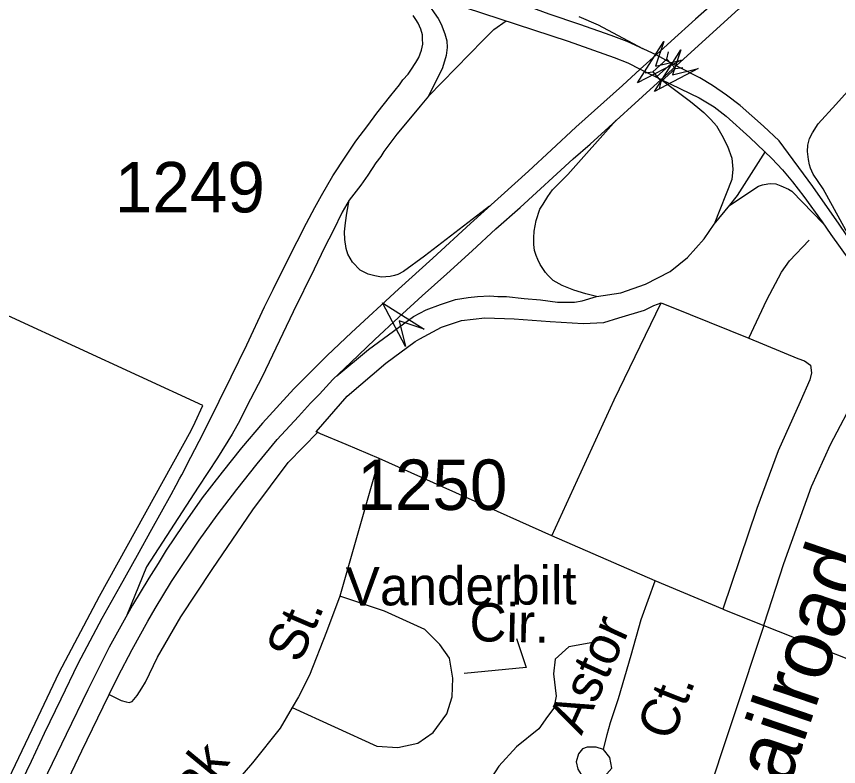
# Model space of a CAD drawing. Extents: x 2260773 to 2342389, y 552869 to 618546.
# Drawn here: x 2295878 to 2297914, y 599147 to 601005 of the extents above; entities that cross this region are included whole.
import ezdxf

# ---------------------------------------------------------------- set-up
doc = ezdxf.new("R2010")
doc.units = 0
for name, color, linetype in [('Exist Boundary Political City Limit New', 7, 'Continuous'), ('Exist Hydrographic Misc Water Feature', 7, 'Continuous'), ('Exist Railroad Mainline', 7, 'Continuous'), ('Exist Railroad Mainline Label', 7, 'Continuous'), ('Exist Road Non-System Type 51', 7, 'Continuous'), ('Exist Road Non-System Type 51 Label', 7, 'Continuous'), ('Exist Road Primary Interstate Ramp 1 Lane Attributed', 7, 'Continuous'), ('Exist Road Primary Interstate Structure Ovrhead Sign Attributed CELL', 7, 'Continuous'), ('Exist Road Primary Interstate Structure Standard Bridge CELL', 7, 'Continuous'), ('Exist Road Primary US Divided Attributed', 7, 'Continuous'), ('Exist Road Primary US Service Attributed', 7, 'Continuous'), ('Exist Road Secondary Structure Standard Bridge Attributed CELL', 7, 'Continuous'), ('Exist Road Secondary Type 51 Attributed', 7, 'Continuous'), ('Exist Road Secondary Type 51 Number Label', 7, 'Continuous'), ('Map Preparation Boundary City Limit Buffer Line', 7, 'Continuous')]:
    doc.layers.add(name, color=color, linetype=linetype)

msp = doc.modelspace()

# ---------------------------------------------------------------- linework, layer by layer
at = {"layer": 'Exist Boundary Political City Limit New'}
msp.add_lwpolyline([(2295816.8, 599028.8), (2295917.5, 599238.1), (2295983.8, 599379.9), (2296084.2, 599568.9), (2296311, 599979.1), (2296321, 600000), (2296340.2, 600041.4), (2295708.2, 600332.1), (2295724.8, 600370), (2295400.5, 600514.7), (2294956.2, 600712.8), (2294754, 600802), (2294588.5, 600875.4), (2294408.8, 600955.1), (2294223.5, 601037.2), (2293856, 601200.2)], dxfattribs=at)
at = {"layer": 'Exist Hydrographic Misc Water Feature'}
msp.add_lwpolyline([(2297333.6, 599467.7), (2297305.7, 599453.6), (2297245.9, 599443.2), (2297212.2, 599412.6), (2297208.7, 599376.6), (2297215.3, 599320.8), (2297209.4, 599290.9), (2297193.8, 599270.6), (2297171.6, 599240.2), (2297116.7, 599195.8), (2297073, 599147.6), (2297045.5, 599105.1)], dxfattribs=at)
at = {"layer": 'Exist Railroad Mainline'}
msp.add_lwpolyline([(2298059.6, 600259), (2298041.3, 600221.8), (2298023.6, 600191.5), (2297893.3, 599943.6), (2297846.2, 599839.4), (2297778.1, 599648.8), (2297729.5, 599498.3), (2297728.8, 599496.1), (2297430.1, 598596.1), (2297256.9, 598090.6)], dxfattribs=at)
at = {"layer": 'Exist Road Non-System Type 51'}
for p, q in [((2296694.9, 599944.5), (2296631.4, 599971)), ((2296776.9, 599910.2), (2296694.9, 599944.5)), ((2296776.9, 599910.2), (2296678.8, 599569)), ((2297204.3, 599718.6), (2296776.9, 599910.2)), ((2297459.7, 599606.4), (2297204.3, 599718.6)), ((2297627.9, 599536.3), (2297459.7, 599606.4)), ((2297627.9, 599536.3), (2297728.8, 599496.1))]:
    msp.add_line(p, q, dxfattribs=at)
for points in [[(2297691.7, 600207.8), (2297736.9, 600302.8), (2297772.7, 600371.4), (2297793, 600399.4), (2297841.2, 600450.9)], [(2296877.3, 600206.3), (2296931.1, 600235.1), (2296980.1, 600251.4), (2297038.5, 600258.4), (2297110.9, 600256.1), (2297199.7, 600249.1), (2297281.4, 600244.4), (2297332.8, 600246.8), (2297370.2, 600258.4), (2297433.3, 600277.1), (2297456.6, 600288.8), (2297475.3, 600295.1)], [(2297204.3, 599718.6), (2297358.5, 600055.1), (2297475.3, 600295.1)], [(2297475.3, 600295.1), (2297546.4, 600266.3), (2297691.7, 600207.8)], [(2296631.4, 599971), (2296620.4, 599975.7), (2296697.5, 600064.5), (2296793.2, 600146.3), (2296865.7, 600200), (2296877.3, 600206.3)], [(2297691.7, 600207.8), (2297813.2, 600157.9), (2297830.3, 600151.7), (2297844.4, 600140.8), (2297847.5, 600122.1), (2297842.8, 600105), (2297819.4, 600050.4), (2297764.9, 599928.9), (2297712, 599785.6), (2297627.9, 599536.3)], [(2297332, 599188.8), (2297341.4, 599226.2), (2297349.2, 599255.8), (2297369.4, 599315), (2297400.5, 599422.5), (2297425.5, 599511.3), (2297459.7, 599606.4)], [(2296678.8, 599569), (2296646.1, 599480.2), (2296604, 599372.7), (2296576.8, 599319.7), (2296561.2, 599293.2)], [(2296561.2, 599293.2), (2296770.7, 599197.5), (2296822.9, 599194), (2296872.6, 599204.4), (2296910.4, 599230.8), (2296943.9, 599277.1), (2296957.5, 599319.2), (2296959.1, 599365.2), (2296950.7, 599415.1), (2296926.4, 599448.8), (2296890, 599486.5), (2296789.7, 599531.5), (2296678.8, 599569)], [(2297728.8, 599496.1), (2297764.9, 599481.7), (2298054.6, 599366.4)], [(2296561.2, 599293.2), (2296531.6, 599241.8), (2296463.1, 599156.1), (2296396.2, 599078.2), (2296369.7, 599053.3)], [(2297332, 599188.8), (2297313.9, 599194.6), (2297291.9, 599194.4), (2297280, 599190.3), (2297270, 599178.3), (2297264.2, 599158.2), (2297268.4, 599140.3), (2297280.6, 599120.5), (2297302.6, 599112.6), (2297324.7, 599114.8), (2297340.5, 599128.9), (2297352.4, 599143), (2297348.2, 599169.1), (2297332, 599188.8)]]:
    msp.add_lwpolyline(points, dxfattribs=at)
at = {"layer": 'Exist Road Non-System Type 51 Label'}
msp.add_lwpolyline([(2297116.5, 599463.5), (2297140.4, 599391.7), (2296987.4, 599377.4)], dxfattribs=at)
at = {"layer": 'Exist Road Primary Interstate Ramp 1 Lane Attributed'}
for points in [[(2296691.3, 601125.6), (2296849.2, 601060.7), (2296891.8, 601038.9), (2296903.7, 601026.8), (2296912.9, 601013.6), (2296922.3, 600999.6), (2296929.7, 600985.6), (2296939.4, 600962.2), (2296944.4, 600944.3), (2296945.1, 600927.7), (2296942.3, 600908.5), (2296933.7, 600878), (2296899, 600807.7)], [(2296899, 600807.7), (2297034.1, 600946.4), (2297060.6, 600972.4), (2297090.8, 600994.4)], [(2297271.4, 601005.1), (2297319.1, 600983.9), (2297428.3, 600925.5)], [(2297474.7, 600848.8), (2297547.5, 600793.9), (2297565.5, 600779.5), (2297580.8, 600766.6), (2297597.6, 600749.4), (2297611.6, 600733.8), (2297625.6, 600710.5), (2297638.9, 600683.7), (2297650.1, 600653.6), (2297652.1, 600626.7), (2297649.7, 600601.1), (2297605.8, 600490.6)], [(2297960, 600424.7), (2297875.9, 600577.6), (2297851.7, 600614.6), (2297845.1, 600628.9), (2297842.5, 600637.3), (2297839.6, 600650.2), (2297837.2, 600670.3), (2297838.4, 600686.1), (2297842.1, 600702.7), (2297849.9, 600716.3), (2297864.1, 600738.6), (2297907.9, 600787.2), (2297944, 600827.2)], [(2296899, 600807.7), (2296878.3, 600782.3), (2296833.5, 600728.9), (2296820.3, 600713.2), (2296803.2, 600690.3), (2296787.8, 600670), (2296780.4, 600658.1), (2296768.6, 600642.1), (2296748.4, 600611.8), (2296731.5, 600587.2), (2296702.1, 600549.5)], [(2297314.8, 600310.8), (2297288.4, 600318), (2297258.4, 600327.2), (2297229.7, 600338.5), (2297207.6, 600350.5), (2297194.9, 600363.3), (2297188.2, 600370.9), (2297175.4, 600390.1), (2297169.4, 600402.5), (2297165, 600412.9), (2297161.6, 600425), (2297159.7, 600439.7), (2297159.3, 600456.8), (2297160.7, 600473), (2297165.3, 600499.6), (2297174.7, 600527.3), (2297182.6, 600539.8), (2297194.2, 600559.2), (2297205.5, 600575.8), (2297244.1, 600613.7), (2297363.3, 600747.6)], [(2297644.6, 600537.6), (2297664.3, 600561.3), (2297733.5, 600670)], [(2297644.6, 600537.6), (2297715.6, 600584.7), (2297726.1, 600587.8), (2297739.4, 600590.5), (2297745.8, 600590.9), (2297759.2, 600590.1), (2297771.3, 600585.1), (2297790.4, 600577.3), (2297798.9, 600571.8), (2297876.2, 600492.1)], [(2296702.1, 600549.5), (2296685, 600520.4), (2296662.7, 600473.8), (2296641, 600432.4), (2296615.9, 600379), (2296563.9, 600273.4), (2296486.5, 600112), (2296447.9, 600037.5), (2296431.1, 600004), (2296412.8, 599970.3), (2296376.2, 599911.5), (2296328.3, 599838.7), (2296200.3, 599641.6), (2296151.8, 599521.6)], [(2297049.9, 600534.6), (2296889.2, 600411), (2296836.9, 600373.3), (2296822.9, 600365.6), (2296814.9, 600363), (2296803.5, 600361), (2296782.6, 600359), (2296765.8, 600362.5), (2296748.9, 600366.5), (2296729.2, 600376.7), (2296710.1, 600396.4), (2296699.2, 600415.9), (2296694.7, 600430.4), (2296691.3, 600452.7), (2296690.4, 600471.6), (2296693, 600493.6), (2296696.7, 600517.8), (2296702.1, 600549.5)], [(2297605.8, 600490.6), (2297644.6, 600537.6)], [(2297314.8, 600310.8), (2297375.3, 600320), (2297435.9, 600341.3), (2297497.3, 600373), (2297540.1, 600407.4), (2297581.7, 600454.3), (2297605.8, 600490.6)], [(2296671.9, 600114.9), (2296750, 600179.6), (2296861.2, 600261.4), (2296892.8, 600278.2), (2296928.4, 600291.4), (2296965.6, 600303.4), (2296997.1, 600308.3), (2297020.4, 600311.3), (2297050.9, 600312.4), (2297070.3, 600311.3), (2297091.8, 600310.8), (2297135.5, 600306.2), (2297175.9, 600302.7), (2297218.3, 600297.2), (2297260.3, 600297.5), (2297279.4, 600300.6), (2297314.8, 600310.8)]]:
    msp.add_lwpolyline(points, dxfattribs=at)
at = {"layer": 'Exist Road Primary Interstate Structure Ovrhead Sign Attributed CELL'}
msp.add_lwpolyline([(2296841.5, 600187.5), (2296785, 600295.6), (2296887.9, 600230.2), (2296826.3, 600250.7)], close=True, dxfattribs=at)
at = {"layer": 'Exist Road Primary Interstate Structure Standard Bridge CELL'}
for p, q in [((2297489.3, 600899.2), (2297493.4, 600917.6)), ((2297464.5, 600855.8), (2297499.8, 600887.5)), ((2297510.2, 600876), (2297528.9, 600878.1)), ((2297435.2, 600865.5), (2297453.9, 600867.6)), ((2297471, 600825.7), (2297475.1, 600844.1))]:
    msp.add_line(p, q, dxfattribs=at)
msp.add_lwpolyline([(2297475.1, 600844.1), (2297510.4, 600875.8), (2297489.3, 600899.3), (2297453.9, 600867.6)], close=True, dxfattribs=at)
at = {"layer": 'Exist Road Primary US Divided Attributed'}
msp.add_line((2297462.4, 600910), (2297422.7, 600874.6), dxfattribs=at)
for points in [[(2297512.1, 600883), (2297667, 601023.8), (2297732, 601078), (2297793.3, 601128.2), (2297854.8, 601175.5), (2297919.2, 601220), (2297954.2, 601242.7), (2298022.3, 601284.7), (2298057.4, 601303.3), (2298129, 601341.5), (2298165.6, 601359.2), (2298201.9, 601375.3), (2298275.7, 601406.5), (2298351.1, 601433.3), (2298426.6, 601457), (2298505.5, 601478.9), (2298584.9, 601497.7), (2298667.6, 601512.9), (2298746.8, 601524.5), (2298864.5, 601539.5), (2299102.2, 601569.1), (2299665.5, 601640.9)], [(2295593.1, 601516.3), (2295724.5, 601467.3), (2295814.9, 601434.9), (2295993.8, 601373.4), (2296146.3, 601318.2), (2296334, 601251), (2296488.1, 601197.1), (2296700.1, 601122.7), (2296904, 601055.8), (2297244.3, 600944.1), (2297358.7, 600903.5), (2297392.1, 600889.7), (2297422.7, 600874.6)], [(2298328, 601479.3), (2298240.8, 601447), (2298203.2, 601431), (2298165.1, 601415.3), (2298103.7, 601385.4), (2298079, 601372.8), (2298057.1, 601362), (2298020.4, 601342.3), (2297981.4, 601320.5), (2297910.7, 601277.3), (2297844.8, 601232.4), (2297776.4, 601182.2), (2297715, 601133.1), (2297650.2, 601078.2), (2297560.2, 600998.5), (2297499.6, 600943.8), (2297462.4, 600910)], [(2297462.4, 600910), (2297390.9, 600942.6), (2297351.4, 600957.6), (2297273.3, 600985.1), (2297197.8, 601010.8), (2297125.7, 601036.8), (2297116.7, 601040.1), (2297084.9, 601051.2), (2297051.3, 601062.3), (2296930.7, 601104.4)], [(2297512.1, 600883), (2297462.4, 600910)], [(2297422.7, 600874.6), (2297379.5, 600833.8), (2297264, 600730.3), (2297203, 600674.2), (2297146, 600621.5), (2297003.1, 600492.3), (2296909.8, 600406.3), (2296824.8, 600329.5), (2296708.3, 600222.2), (2296648, 600164.9), (2296565.4, 600082.3), (2296487.3, 599997.6), (2296435.2, 599936), (2296387.7, 599876.3), (2296361.2, 599841.8), (2296338.3, 599812.3), (2296290.1, 599744), (2296249.3, 599683), (2296229.2, 599649.5), (2296205.7, 599613.5), (2296165.5, 599546.2), (2296107.9, 599442.5), (2296054.8, 599336.4), (2296001.2, 599226.1), (2295897.8, 599011.8)], [(2297422.7, 600874.6), (2297474.7, 600848.8)], [(2297474.7, 600848.8), (2297512.1, 600883)], [(2298042.5, 600303.9), (2297985.1, 600387.9), (2297915.4, 600490.1), (2297850.4, 600583.5), (2297767.5, 600696.7), (2297728.7, 600733.5), (2297670.4, 600784.7), (2297636.5, 600809.9), (2297602.4, 600833.7), (2297570.4, 600852.8), (2297512.1, 600883)], [(2296107.9, 599325), (2296129.5, 599369), (2296164.6, 599436.3), (2296203.6, 599506.4), (2296222.1, 599538.2), (2296262.2, 599604.7), (2296330.5, 599707.4), (2296375.7, 599769.6), (2296423.8, 599833.2), (2296474.1, 599896.5), (2296524.3, 599956.5), (2296576.4, 600013.6), (2296606.4, 600046.9), (2296628.4, 600069.3), (2296662.1, 600105.4), (2296706.5, 600147.7), (2296765.4, 600204.5), (2296824.4, 600259.1), (2296883.3, 600313), (2296944, 600367.5), (2297006.9, 600424.7), (2297065.5, 600478.5), (2297125.9, 600531.7), (2297256.8, 600652.4), (2297298.7, 600688.9), (2297474.7, 600848.8)], [(2297474.7, 600848.8), (2297568.7, 600803.1), (2297606.3, 600781.4), (2297636.2, 600757.6), (2297694.5, 600705.2), (2297749.4, 600653.4), (2297775.7, 600624.8), (2297800.1, 600595.4), (2297828.4, 600559.3), (2297873.5, 600496), (2297895.3, 600464.9), (2297941.2, 600400.5), (2297987.2, 600332.7), (2298022.9, 600281.1)], [(2295462.8, 598090.9), (2295495.8, 598135.2), (2295538.5, 598202), (2295600.6, 598303.3), (2295620.5, 598338), (2295639, 598370.9), (2295695.7, 598475.4), (2295732.9, 598547.7), (2295766.2, 598614.9), (2295818.6, 598725.2), (2295852.6, 598794.6), (2295922, 598940.6), (2295990.4, 599081.6), (2296040.2, 599185.4), (2296093, 599294.9), (2296107.9, 599325)]]:
    msp.add_lwpolyline(points, dxfattribs=at)
at = {"layer": 'Exist Road Primary US Service Attributed'}
msp.add_lwpolyline([(2295879.8, 599086.7), (2295915.1, 599160.2), (2295947.9, 599229), (2295989.3, 599314.2), (2296030.8, 599402.1), (2296090.4, 599514.6), (2296134.7, 599593.8), (2296178, 599670.3), (2296213.7, 599735), (2296261, 599820.9), (2296273.6, 599843.9), (2296281.7, 599859.4), (2296288.1, 599869.6), (2296310.2, 599913.3), (2296340.9, 599971.7), (2296380.3, 600052.2), (2296409.9, 600112.4), (2296448.5, 600191.7), (2296492.8, 600285.2), (2296514.1, 600328.8), (2296550.5, 600402.3), (2296596.3, 600493), (2296616.9, 600532), (2296633.5, 600561.6), (2296662.1, 600610.4), (2296693.6, 600658.7), (2296718.9, 600696.2), (2296748.1, 600735), (2296771.1, 600765.5), (2296805.2, 600809.5), (2296826.5, 600835.5), (2296835.4, 600847.7), (2296848, 600862.1), (2296855, 600872.2), (2296867.2, 600890.5), (2296874.4, 600903.3), (2296881.2, 600921.4), (2296884.4, 600936.3), (2296884.2, 600949.3), (2296883.8, 600959.5), (2296880, 600973.5), (2296873.1, 600988), (2296867.6, 600997.8), (2296860.8, 601007)], dxfattribs=at)
at = {"layer": 'Exist Road Secondary Structure Standard Bridge Attributed CELL'}
for points in [[(2297524.2, 600896.6), (2297416.1, 600840.2), (2297481.5, 600943.1), (2297461, 600881.4)], [(2297566.5, 600875.7), (2297458.6, 600818.8), (2297523.6, 600922), (2297503.3, 600860.2)]]:
    msp.add_lwpolyline(points, close=True, dxfattribs=at)
at = {"layer": 'Exist Road Secondary Type 51 Attributed'}
msp.add_lwpolyline([(2296107.9, 599325), (2296137.9, 599309.9), (2296149.6, 599307), (2296157.3, 599305.5), (2296164.4, 599308), (2296177.3, 599322.8), (2296189.1, 599340.6), (2296198, 599355.5), (2296227.7, 599417.8), (2296285.6, 599517.2), (2296362.7, 599634.5), (2296463.6, 599782.9), (2296551.1, 599900.1), (2296625.3, 599975.8)], dxfattribs=at)
at = {"layer": 'Map Preparation Boundary City Limit Buffer Line'}
msp.add_lwpolyline([(2295816.8, 599028.8), (2295917.5, 599238.1), (2295983.8, 599379.9), (2296084.2, 599568.9), (2296311, 599979.1), (2296321, 600000), (2296340.2, 600041.4), (2295708.2, 600332.1), (2295724.8, 600370), (2295400.5, 600514.7), (2294956.2, 600712.8), (2294754, 600802), (2294588.5, 600875.4), (2294408.8, 600955.1), (2294223.5, 601037.2), (2293856, 601200.2)], dxfattribs=at)

# ---------------------------------------------------------------- texts
at = {"layer": 'Exist Railroad Mainline Label'}
msp.add_text('Railroad', height=150, rotation=71.1618, dxfattribs=at).set_placement((2297744.2, 598959.2))
at = {"layer": 'Exist Road Non-System Type 51 Label'}
for s, rotation, p in [('Vanderbilt', 0.3298, (2296693.9, 599545.3)), ('Cir.', 358.8498, (2296999.4, 599457.4)), ('St.', 66.7483, (2296580.3, 599399.5)), ('Astor', 65.503, (2297277.6, 599222.3)), ('Ct.', 68.4533, (2297500.9, 599206.5)), ('Oak', 50.5118, (2296260.9, 598978.2))]:
    msp.add_text(s, height=95, rotation=rotation, dxfattribs=at).set_placement(p)
at = {"layer": 'Exist Road Secondary Type 51 Number Label'}
for s, p in [('1249', (2296121.6, 600519.5)), ('1250', (2296722.4, 599782.3))]:
    msp.add_text(s, height=125, dxfattribs=at).set_placement(p)

doc.saveas('drawing.dxf')
